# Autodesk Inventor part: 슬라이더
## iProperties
Company: 한국ATC센터
Created: 2015-04
Part Number: 슬라이더
Document SubType Name: Modeling
Designer: KYOUNG IL JANG
Density: 7.85 g/cm^3
Material: 강
Author: KYOUNG IL JANG
